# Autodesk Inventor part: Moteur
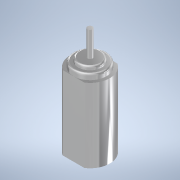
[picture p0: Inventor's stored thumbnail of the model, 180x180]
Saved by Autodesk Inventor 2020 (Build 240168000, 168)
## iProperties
Created: 2002-01
Part Number: Moteur
Material: Aluminium 6061
Document SubType Name: Modélisation
Designer: Philippe
Mass: 0.846897 g
Surface Area: 2.82951 cm^2
Volume: 0.313666 cm^3
Density: 2.7 g/cm^3
Appearance: Aluminium - Plat
Shininess: 20.0
Angle Display Precision: 2
Document Length Units: 11269
Document Angle Units: 11279
Document Time Units: 11290
Document Mass Units: 11283
Document Length Units Precision: 3
Document Angle Units Precision: 2
Density: 0.0
Volumn: 0.0
Area: 0.0
PropertySet Name: Model Information
Control State: 0
Master: False
Checked Out: False
Author: Philippe
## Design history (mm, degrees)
sketch "Esquisse1"
  geometry: L1 (-3.134, 1.173)-(0.182, 1.173); L2 (-3.134, -3.827)-(0.182, -3.827); L3 (-1.476, -1.327)-(-3.356, -1.327); A1 r 3 centre (-1.476, -1.327) between (-3.134, 1.173) and (-3.134, -3.827); A2 r 3 centre (-1.476, -1.327) between (0.182, -3.827) and (0.182, 1.173)
  constraints: 6 end point, 4 point on circle, 2 centre point, 2 parallel, 1 concentric, 1 horizontal, 2 other
  dimensions: "d0" = 5 distance between parallel lines of L2 L1; "d1" = 3 radius of A2
extrude "Extrusion1" new body sketch "Esquisse1" distance "d2" = 11.2; taper "d3" = 0 deg
sketch "Esquisse2"
  geometry: C1 r 2.5 at (-1.476, -1.327); A1 r 3 centre (-1.476, -1.327) between (-3.134, 1.173) and (-3.134, -3.827) reference
  constraints: 1 centre point, 1 coincident
  dimensions: "d6" = 5 diameter of C1
extrude "Extrusion2" join sketch "Esquisse2" distance "d4" = 0.8; taper "d5" = 0 deg
sketch "Esquisse3"
  geometry: C1 r 2.5 at (0, 0) reference; C2 r 1.8 at (0, 0)
  constraints: 1 centre point, 1 coincident
  dimensions: "d7" = 3.6 diameter of C2
extrude "Extrusion3" join sketch "Esquisse3" distance "d8" = 0.5; taper "d9" = 0 deg
sketch "Esquisse4"
  geometry: C1 r 1.8 at (0, 0) reference; C2 r 0.4 at (0, 0)
  constraints: 1 centre point, 1 coincident
  dimensions: "d10" = 0.8 diameter of C2
extrude "Extrusion4" join sketch "Esquisse4" distance "d11" = 3.8; taper "d12" = 0 deg
fillet "Congé1" dims "d13" = 0.3
node "Solide1"
node "Corps solides"
node "Corps surfaciques"
